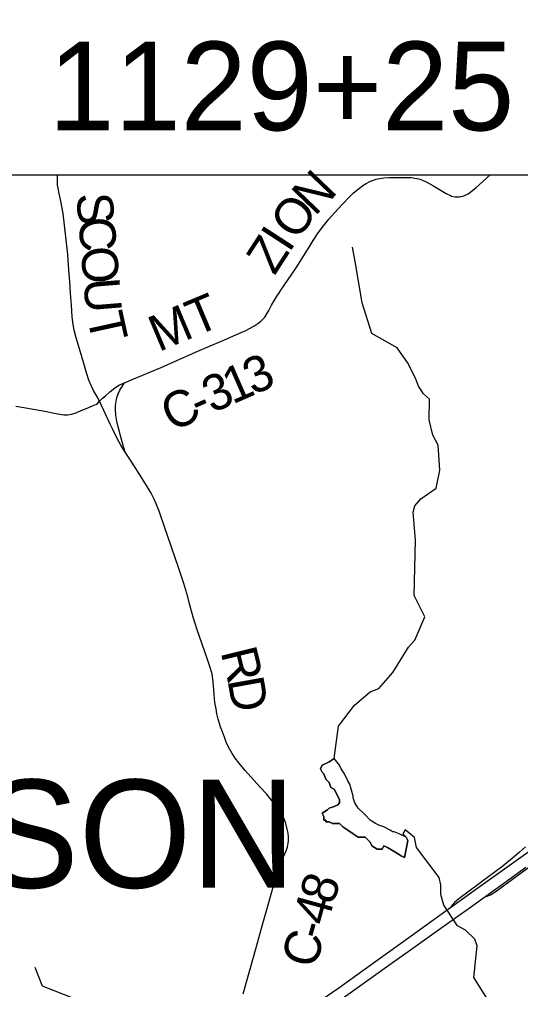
# Model space of a CAD drawing. Extents: x 0 to 34, y 0 to 22.
# Drawn here: x 24.883 to 25.673, y 15.788 to 17.319 of the extents above; entities that cross this region are included whole.
import ezdxf

# ---------------------------------------------------------------- set-up
doc = ezdxf.new("R2010")
doc.units = 0
for name, color, linetype in [('GM_X_County_Road', 7, 'Continuous'), ('GM_X_County_Road_Text', 7, 'Continuous'), ('GM_X_Interchange_Ramps', 7, 'Continuous'), ('GM_X_Minor_Lake', 7, 'Continuous'), ('GM_X_Minor_River', 7, 'Continuous'), ('GM_X_State_Route', 7, 'Continuous'), ('GM_X_Township_Road', 7, 'Continuous'), ('GM_X_Township_Text', 7, 'Continuous'), ('SH_Text', 7, 'Continuous')]:
    doc.layers.add(name, color=color, linetype=linetype)

msp = doc.modelspace()

# ---------------------------------------------------------------- linework, layer by layer
at = {"layer": 'GM_X_County_Road'}
for points in [[(25.0091, 16.7162), (25.0052, 16.7231), (24.9996, 16.733), (24.9958, 16.7413), (24.9925, 16.7496), (24.9887, 16.7611), (24.9854, 16.7721), (24.9818, 16.7848), (24.9778, 16.7992), (24.9725, 16.8165), (24.9694, 16.8285), (24.9676, 16.8373), (24.9661, 16.8496), (24.9647, 16.8681), (24.9635, 16.8867), (24.9623, 16.9052), (24.9614, 16.9172), (24.9598, 16.9386), (24.9589, 16.9478), (24.9568, 16.9663), (24.9558, 16.9755), (24.9539, 16.994), (24.9516, 17.0125), (24.948, 17.0319), (24.9455, 17.0441), (24.9438, 17.0527), (24.943, 17.0571), (24.9427, 17.062), (24.943, 17.0679), (24.943, 17.0737)], [(25.0484, 16.7456), (25.0607, 16.7505), (25.1065, 16.7696), (25.1264, 16.7783), (25.1603, 16.7937), (25.1859, 16.805), (25.2059, 16.8134), (25.2285, 16.8231), (25.2399, 16.8281), (25.2454, 16.8309), (25.2523, 16.8346), (25.2587, 16.8388), (25.2633, 16.8425), (25.2656, 16.8445), (25.2676, 16.8467), (25.2695, 16.8491), (25.2727, 16.8543), (25.2758, 16.8596), (25.2803, 16.8677), (25.2819, 16.8704), (25.2834, 16.8731), (25.2865, 16.8785), (25.2898, 16.8838), (25.2915, 16.8863), (25.2932, 16.8889), (25.295, 16.8913), (25.3055, 16.9068), (25.3189, 16.9267), (25.3305, 16.9451), (25.3394, 16.9596), (25.3461, 16.97), (25.3539, 16.982), (25.3621, 16.9928), (25.3707, 17.0034), (25.3796, 17.0137), (25.3921, 17.0273), (25.4027, 17.0384), (25.4095, 17.0449), (25.4166, 17.051), (25.4241, 17.0567), (25.4293, 17.0601), (25.4351, 17.0629), (25.4392, 17.0647), (25.445, 17.0667), (25.4505, 17.0679), (25.4573, 17.0686), (25.4656, 17.0692), (25.475, 17.0695), (25.4869, 17.0695), (25.5005, 17.0691), (25.5092, 17.068), (25.5123, 17.0673), (25.5154, 17.0664), (25.5184, 17.0653), (25.524, 17.0626), (25.5346, 17.0568), (25.5372, 17.0553), (25.5451, 17.0503), (25.5557, 17.0439), (25.5584, 17.0425), (25.5612, 17.0412), (25.5641, 17.0401), (25.567, 17.0394), (25.5699, 17.0388), (25.5729, 17.0386), (25.5759, 17.0388), (25.5788, 17.0393), (25.5818, 17.04), (25.5846, 17.041), (25.5874, 17.0423), (25.59, 17.0438), (25.595, 17.0473), (25.6021, 17.0532), (25.6247, 17.0737)], [(25.0091, 16.7162), (25.0113, 16.7186), (25.0137, 16.7212), (25.0186, 16.7249), (25.0256, 16.7309), (25.0328, 16.7368), (25.0379, 16.7404), (25.0406, 16.742), (25.0446, 16.744), (25.0484, 16.7456)], [(25.0496, 16.6358), (25.0466, 16.6463), (25.0415, 16.6639), (25.0383, 16.6759), (25.0364, 16.685), (25.035, 16.6942), (25.0344, 16.7035), (25.0345, 16.7098), (25.0352, 16.716), (25.0365, 16.7221), (25.0374, 16.7251), (25.0385, 16.728), (25.0412, 16.7336), (25.0428, 16.7363), (25.0484, 16.7456)], [(25.0496, 16.6358), (25.0426, 16.6468), (25.0373, 16.6565), (25.0299, 16.6718), (25.0259, 16.6804), (25.0193, 16.6947), (25.0091, 16.7162)], [(25.2355, 15.7813), (25.2565, 15.856), (25.2656, 15.8889), (25.2748, 15.9218), (25.2835, 15.9516), (25.2886, 15.9695), (25.2923, 15.9812), (25.2946, 15.9869), (25.2982, 15.9954), (25.3032, 16.0068), (25.3052, 16.0128), (25.306, 16.0158), (25.3066, 16.019), (25.3069, 16.0221), (25.307, 16.0253), (25.3069, 16.0284), (25.3063, 16.0347), (25.3051, 16.0409), (25.3025, 16.0499), (25.3004, 16.0558), (25.2978, 16.0615), (25.2947, 16.0669), (25.2913, 16.0721), (25.2859, 16.0797), (25.2803, 16.0871), (25.2724, 16.0967), (25.2619, 16.1082), (25.2388, 16.1339), (25.2285, 16.1459), (25.223, 16.1531), (25.2181, 16.1605), (25.2138, 16.1681), (25.2095, 16.1769), (25.206, 16.1861), (25.2028, 16.1946), (25.2005, 16.2012), (25.1982, 16.2077), (25.196, 16.2147), (25.1942, 16.223), (25.1927, 16.2311), (25.1911, 16.2412), (25.1899, 16.2536), (25.1887, 16.2679), (25.1879, 16.2777), (25.1864, 16.2858), (25.1836, 16.2964), (25.179, 16.3103), (25.1711, 16.3328), (25.1632, 16.3557), (25.1568, 16.3756), (25.1511, 16.3967), (25.1483, 16.4079), (25.1419, 16.4287), (25.1341, 16.4522), (25.122, 16.4874), (25.112, 16.5167), (25.103, 16.543), (25.0986, 16.5546), (25.0948, 16.563), (25.0904, 16.5712), (25.0841, 16.5819), (25.0727, 16.6003), (25.0627, 16.616), (25.0558, 16.6263), (25.0496, 16.6358)]]:
    msp.add_lwpolyline(points, dxfattribs=at)
at = {"layer": 'GM_X_Interchange_Ramps'}
for points in [[(25.6147, 15.9334), (25.6254, 15.9375), (25.6324, 15.9416), (25.6817, 15.978), (25.7032, 15.993), (25.7285, 16.0109), (25.7441, 16.0211), (25.7627, 16.0324), (25.7788, 16.0416), (25.7926, 16.0488), (25.801, 16.0528), (25.8096, 16.0565), (25.8183, 16.0596), (25.8273, 16.0621), (25.8364, 16.064), (25.8456, 16.0654), (25.8548, 16.066), (25.8673, 16.066), (25.9044, 16.0644), (25.9234, 16.0637), (25.9458, 16.0619)], [(25.6804, 16.0135), (25.6713, 16.0051), (25.6595, 15.9949), (25.6425, 15.9814), (25.6128, 15.959), (25.6082, 15.9556), (25.5754, 15.931), (25.5685, 15.9257), (25.565, 15.9214), (25.5625, 15.9174)]]:
    msp.add_lwpolyline(points, dxfattribs=at)
at = {"layer": 'GM_X_Minor_Lake'}
for points in [[(25.3791, 16.1527), (25.371, 16.1473), (25.3656, 16.1446), (25.3602, 16.1419), (25.3575, 16.1365), (25.3602, 16.1311), (25.3629, 16.1284), (25.3656, 16.1203), (25.371, 16.1149), (25.3737, 16.1068), (25.3791, 16.1041), (25.3872, 16.0879), (25.3872, 16.0825), (25.3845, 16.0798), (25.3791, 16.0771), (25.371, 16.0744), (25.3683, 16.0717), (25.3602, 16.0663), (25.3629, 16.0609), (25.3629, 16.0555), (25.3656, 16.0555), (25.3656, 16.0529), (25.3683, 16.0529), (25.371, 16.0529), (25.3764, 16.0501), (25.3845, 16.0501), (25.3872, 16.0501), (25.3926, 16.0447), (25.4007, 16.0394), (25.4088, 16.034), (25.4169, 16.0286), (25.4277, 16.0286), (25.4358, 16.0205), (25.4385, 16.0151), (25.4466, 16.0097), (25.4547, 16.0097), (25.4574, 16.0151), (25.4628, 16.0124), (25.4762, 16.0043), (25.4843, 15.9989), (25.4897, 15.9962), (25.4924, 16.0097), (25.4951, 16.0232), (25.4924, 16.0285)], [(25.487, 16.0339), (25.4924, 16.0285), (25.4951, 16.0232), (25.4924, 16.0097), (25.4897, 15.9962), (25.4843, 15.9989), (25.4762, 16.0043), (25.4628, 16.0124), (25.4574, 16.0151), (25.4547, 16.0097), (25.4466, 16.0097), (25.4385, 16.0151), (25.4358, 16.0205), (25.4277, 16.0286), (25.4169, 16.0286), (25.4088, 16.034), (25.4007, 16.0394), (25.3926, 16.0447), (25.3872, 16.0501), (25.3845, 16.0501), (25.3764, 16.0501), (25.371, 16.0529), (25.3683, 16.0529), (25.3656, 16.0529), (25.3656, 16.0555), (25.3629, 16.0555), (25.3629, 16.0609), (25.3602, 16.0663), (25.3683, 16.0717), (25.371, 16.0744), (25.3791, 16.0771), (25.3845, 16.0798), (25.3872, 16.0825), (25.3872, 16.0879), (25.3791, 16.1041), (25.3737, 16.1068), (25.371, 16.1149), (25.3656, 16.1203), (25.3629, 16.1284), (25.3602, 16.1311), (25.3575, 16.1365), (25.3602, 16.1419), (25.3656, 16.1446), (25.371, 16.1473), (25.3791, 16.1527)], [(25.4924, 16.0285), (25.4816, 16.0339), (25.4736, 16.0367), (25.4708, 16.0367), (25.4682, 16.0393), (25.4574, 16.0447), (25.4493, 16.0475), (25.4439, 16.0501), (25.4358, 16.0555), (25.4277, 16.0636), (25.425, 16.0663), (25.4169, 16.0744), (25.4115, 16.0825), (25.4088, 16.0906), (25.4088, 16.0933), (25.4034, 16.1122), (25.4007, 16.1176), (25.3953, 16.1284), (25.3899, 16.1365), (25.3872, 16.1419), (25.3791, 16.1527)]]:
    msp.add_lwpolyline(points, dxfattribs=at)
at = {"layer": 'GM_X_Minor_River'}
for points in [[(25.3791, 16.1527), (25.3859, 16.2036), (25.4108, 16.2366), (25.4357, 16.258), (25.4493, 16.263), (25.4715, 16.2884), (25.4959, 16.3284), (25.5061, 16.3394), (25.5218, 16.3763), (25.505, 16.41), (25.5069, 16.4972), (25.5037, 16.5412), (25.5063, 16.5511), (25.5154, 16.5621), (25.5399, 16.5793), (25.5455, 16.6074), (25.5426, 16.6468), (25.5346, 16.6627), (25.5285, 16.687), (25.5294, 16.7196), (25.5196, 16.7279), (25.5119, 16.7401), (25.5073, 16.7526), (25.4947, 16.7772), (25.478, 16.8006), (25.4385, 16.8233), (25.4232, 16.8714), (25.4123, 16.9366), (25.408, 16.9594)], [(25.5744, 15.6029), (25.5834, 15.6306), (25.5935, 15.6481), (25.6028, 15.6785), (25.5986, 15.7031), (25.5936, 15.7137), (25.5928, 15.727), (25.5946, 15.7365), (25.6051, 15.7566), (25.6153, 15.7623), (25.6206, 15.773), (25.5993, 15.8071), (25.6043, 15.8571), (25.6005, 15.8678), (25.5861, 15.8817), (25.5735, 15.8889), (25.5518, 15.9215), (25.5468, 15.9381), (25.5471, 15.9533), (25.5444, 15.9647), (25.5087, 16.012), (25.5056, 16.0279), (25.4907, 16.04), (25.487, 16.0339)], [(25.5761, 15.6015), (25.5645, 15.6263), (25.5549, 15.6385), (25.5447, 15.6449), (25.4905, 15.6515), (25.4773, 15.656), (25.4336, 15.6817), (25.4184, 15.6915), (25.3942, 15.6963), (25.354, 15.7163), (25.2896, 15.7146), (25.2359, 15.706), (25.1806, 15.7119), (25.1494, 15.7384), (25.101, 15.734), (25.0912, 15.7351), (25.0813, 15.7416), (25.0514, 15.7456), (25.0408, 15.7471), (24.9975, 15.7674), (24.9714, 15.773), (24.919, 15.7937), (24.9079, 15.8229)]]:
    msp.add_lwpolyline(points, dxfattribs=at)
at = {"layer": 'GM_X_State_Route'}
for points in [[(25.358, 15.7713), (25.3861, 15.7908), (25.4239, 15.8181), (25.487, 15.8634), (25.5552, 15.9122), (25.5625, 15.9174), (25.6056, 15.9485), (25.9511, 16.1955), (25.999, 16.2298), (26.0646, 16.2769), (26.1101, 16.3094), (26.1455, 16.3346), (26.1859, 16.3635), (26.2005, 16.374), (26.2315, 16.3964), (26.259, 16.4161), (26.3121, 16.454), (26.3576, 16.4865), (26.4031, 16.5189), (26.4511, 16.5533), (26.494, 16.5841), (26.5368, 16.615), (26.6554, 16.7), (26.7739, 16.7852)], [(25.3931, 15.775), (25.4336, 15.8038), (25.4689, 15.829), (25.4992, 15.8507), (25.5473, 15.8851), (25.5598, 15.8941), (25.5952, 15.9194), (25.6147, 15.9334), (25.618, 15.9357), (25.6558, 15.9629), (25.6809, 15.9812)]]:
    msp.add_lwpolyline(points, dxfattribs=at)
at = {"layer": 'GM_X_Township_Road'}
msp.add_lwpolyline([(24.8774, 16.7088), (24.8896, 16.7066), (24.9048, 16.7038), (24.9228, 16.7005), (24.9378, 16.6975), (24.9468, 16.6957), (24.9529, 16.6949), (24.9559, 16.6948), (24.9589, 16.6949), (24.9648, 16.6959), (24.9707, 16.6976), (24.9793, 16.701), (24.9932, 16.707), (24.9991, 16.7094), (25.0045, 16.7116), (25.0067, 16.7132), (25.0091, 16.7162)], dxfattribs=at)
at = {"layer": 'SH_Text'}
msp.add_lwpolyline([(24.3906, 17.0737), (25.8632, 17.0737), (25.8632, 17.5637), (24.3906, 17.5637)], close=True, dxfattribs=at)

# ---------------------------------------------------------------- texts
at = {"layer": 'GM_X_County_Road_Text'}
for s, height, rotation, p in [('N', 0.0568, 46.1721, (25.3484, 17.007)), ('S', 0.0568, 274.7475, (24.9723, 17.0431)), ('O', 0.0568, 53.8885, (25.3203, 16.9682)), ('C', 0.0568, 274.7474, (24.9755, 17.0049)), ('I', 0.0568, 56.9768, (25.308, 16.9493)), ('Z', 0.0568, 57.1551, (25.285, 16.9136)), ('O', 0.0568, 274.7491, (24.9793, 16.9584)), ('U', 0.0568, 274.8228, (24.9835, 16.9085)), ('MT', 0.05682, 22.7872, (25.1022, 16.7937)), ('T', 0.0568, 282.4088, (24.9889, 16.8505)), ('3', 0.0568, 24.2253, (25.2513, 16.7253)), ('3', 0.0568, 23.6359, (25.1866, 16.697)), ('1', 0.0568, 23.6243, (25.2186, 16.711)), ('C', 0.0568, 26.504, (25.1242, 16.667)), ('-', 0.0568, 24.0647, (25.1654, 16.6875)), ('R', 0.0568, 283.8138, (25.1997, 16.3209)), ('D', 0.0568, 280.1361, (25.2106, 16.2766)), ('8', 0.0568, 72.6084, (25.3772, 15.9202)), ('4', 0.0568, 74.5335, (25.368, 15.887)), ('-', 0.0568, 74.5929, (25.3618, 15.8645)), ('C', 0.0568, 74.6138, (25.3494, 15.8195))]:
    msp.add_text(s, height=height, rotation=rotation, dxfattribs=at).set_placement(p)
at = {"layer": 'GM_X_Township_Text'}
msp.add_text('JACKSON', height=0.17045, rotation=0, dxfattribs=at).set_placement((24.2418, 15.9487))
at = {"layer": 'SH_Text'}
msp.add_text('STA. 1129+25', height=0.14, dxfattribs=at).set_placement((24.4606, 17.1437))

doc.saveas('drawing.dxf')
